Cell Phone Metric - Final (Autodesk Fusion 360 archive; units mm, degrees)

design "Cell Phone Metric - Final" references "Cell Phone Stand - Metric Assembly", "Vise"
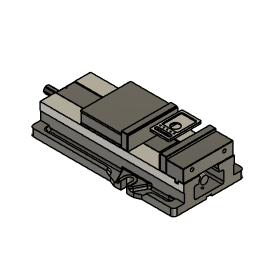
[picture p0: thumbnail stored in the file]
external_derived "ExternalDerived1"
align "Align1"
sketch "Sketch1" plane through (0, 0, 0) normal (0, 0, -1) x axis (1, 0, 0)
  line L1 (30, 46.5) -> (30, -46.5)
  line L2 (-26.5, 50) -> (26.5, 50)
  line L3 (-30, -46.5) -> (-30, 46.5)
  line L4 (26.5, -50) -> (-26.5, -50)
  line L5 (-23.5, 38.5) -> (-23.5, 36)
  line L6 (20, 42) -> (-20, 42)
  line L7 (23.5, 36) -> (23.5, 38.5)
  line L8 (-20, 32.5) -> (20, 32.5)
  line L9 (-50.8, -55) -> (50.8, -55)
  line L10 (-50.8, 55) -> (-50.8, -55)
  line L11 (50.8, 55) -> (-50.8, 55)
  line L12 (50.8, -55) -> (50.8, 55)
  line L13 (-50.8, 55) -> (50.8, -55)
  line L14 (50.8, 55) -> (-50.8, -55)
  arc A1 centre (26.5, -46.5) radius 3.5 clockwise from (30, -46.5) to (26.5, -50)
  arc A2 centre (26.5, 46.5) radius 3.5 clockwise from (26.5, 50) to (30, 46.5)
  arc A3 centre (-26.5, 46.5) radius 3.5 clockwise from (-30, 46.5) to (-26.5, 50)
  arc A4 centre (-26.5, -46.5) radius 3.5 clockwise from (-26.5, -50) to (-30, -46.5)
  circle C1 centre (10.5, 25) radius 2.117
  circle C2 centre (-10.5, 25) radius 2.117
  circle C3 centre (-21, 25) radius 2.117
  circle C4 centre (0, 25) radius 2.117
  circle C5 centre (21, 25) radius 2.117
  arc A5 centre (-20, 38.5) radius 3.5 clockwise from (-23.5, 38.5) to (-20, 42)
  arc A6 centre (20, 38.5) radius 3.5 clockwise from (20, 42) to (23.5, 38.5)
  arc A7 centre (20, 36) radius 3.5 clockwise from (23.5, 36) to (20, 32.5)
  arc A8 centre (-20, 36) radius 3.5 clockwise from (-20, 32.5) to (-23.5, 36)
  circle C6 centre (0, 0) radius 12.5
  point P36 (0, 0)
  point P1 (0, 0)
  point P34 (-50.8, 55)
  point P35 (50.8, 55)
  point P32 (50.8, -55)
  horizontal L9
  perpendicular L9 L10
  parallel L9 L11
  parallel L10 L12
  coincident L13 P36
  coincident L14 P36
  coincident P1 P36
  dimension "d1" distance P34 P35 = 101.6
  dimension "d2" distance P32 P35 = 110
extrude "Extrude1" new body sketch "Sketch1" profile of L9 L10 L11 L12 against normal blind 6 bodies "Stock"
component_insert "Component Insert"
position "Position1"
ground "Pin"
position "Position2"
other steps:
derived_base_feature "Derived Base Feature" bodies "Main Body"
named bodies: "Main Body", "Stock"

design "Vise"
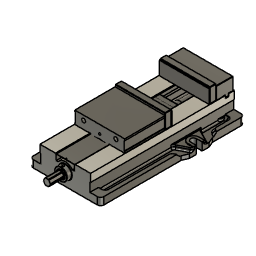
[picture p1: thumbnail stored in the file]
description: HaasClamp
base_feature "Base Feature1"
base_feature "Base Feature1"
base_feature "Base Feature1"
base_feature "Base Feature1"
base_feature "Base Feature1"
base_feature "Base Feature1"
base_feature "Base Feature1"
base_feature "Base Feature1"
base_feature "Base Feature1"
base_feature "Base Feature1"
as_built_joint "As-built1"
as_built_joint "As-built2"
as_built_joint "As-built3"
joint_origin "JointOrigin1" OffsetX 0 OffsetY 0 OffsetZ 0 AngleZ 0
joint "Assemble1" alignAngle 180 alignOffsetX 0 alignOffsetY 0 alignOffsetZ 0 (= "jaw_width_haas_050002") SlideMaximum 22.5 SlideMinimum 0
position "Position1"
sketch "Sketch1" plane through (0, -72.5, 0) normal (0, -1, 0) x axis (1, 0, 0)
  line L1 (75, 73) -> (-75, 73)
  line L2 (76, 74) -> (75, 73)
  line L3 (76, 116.5) -> (76, 74)
  line L4 (75, 117.5) -> (76, 116.5)
  line L5 (-75, 117.5) -> (75, 117.5)
  line L6 (-76, 116.5) -> (-75, 117.5)
  line L7 (-76, 74) -> (-76, 116.5)
  line L8 (-75, 73) -> (-76, 74)
  line L9 (76.4, 114.275) -> (-76, 114.275)
  line L10 (76.4, 73) -> (76.4, 114.275)
  line L11 (-76, 73) -> (76.4, 73)
  line L12 (-76, 114.275) -> (-76, 73)
  circle C1 centre (49.21, 96.8) radius 11
  circle C2 centre (-49.21, 96.8) radius 11
  point P14 (76.4, 73)
  point P12 (-76, 114.275)
  point P13 (76.4, 114.275)
  horizontal L9
  vertical L10
  horizontal L11
  vertical L12
  coincident L1 P14
  coincident L7 P12
  dimension "d16" distance P12 P13 = 152.4
  dimension "d17" distance P13 P14 = 41.275
place_component sketch "Sketch1"
extrude "Extrude1" new body sketch "Sketch1" profile of L1 L2 L3 L7 L8 C1 C2 L9 L11 L12 along normal blind 3.175
place_component sketch "Sketch1"
extrude "Extrude1" sketch "Sketch1" profile of L1 L2 L3 L7 L8 C1 C2 L9 L11 L12 blind -3.175
as_built_joint "As-built5"
as_built_joint "As-built6"
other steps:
create_component "CreateComponent1"
create_component "CreateComponent2"
create_component "CreateComponent3"
create_component "CreateComponent4"
create_component "CreateComponent5"
create_component "CreateComponent6"
create_component "CreateComponent7"
create_component "CreateComponent8"
create_component "CreateComponent9"
create_component "CreateComponent10"
joint_origin "JointOrigin10"
joint_origin "JointOrigin11"
create_component "CreateComponent11" sketch "Sketch1"
create_component "CreateComponent12" sketch "Sketch1"

design "Cell Phone Stand - Metric Assembly"
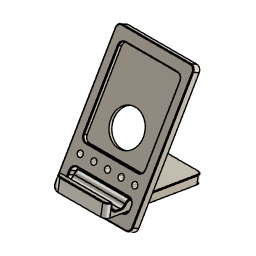
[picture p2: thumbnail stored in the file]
sketch "Main Body Sketch" plane through (0, 0, 0) normal (0, 1, 0) x axis (1, 0, 0)
  line L1 (30, 0) -> (-30, 0)
  line L2 (30, -100) -> (30, 0)
  line L3 (-30, -100) -> (30, -100)
  line L4 (-30, 0) -> (-30, -100)
  line L5 (30, -100) -> (-30, 0)
  line L6 (-30, -100) -> (30, 0)
  line L7 (23.5, -17.5) -> (-23.5, -17.5)
  line L8 (23.5, -8) -> (23.5, -17.5)
  line L9 (-23.5, -8) -> (23.5, -8)
  line L10 (-23.5, -17.5) -> (-23.5, -8)
  line L11 (0, 0) -> (0, -8)
  line L12 (23.5, -92) -> (-23.5, -92)
  line L13 (23.5, -32) -> (23.5, -92)
  line L14 (-23.5, -32) -> (23.5, -32)
  line L15 (-23.5, -92) -> (-23.5, -32)
  line L16 (0, -62.5) -> (0, -50)
  line L17 (17.2022, -62.0451) -> (0, -50)
  line L18 (21, -50) -> (0, -50)
  line L19 (17.2022, -37.9549) -> (0, -50)
  circle C1 centre (0, -50) radius 12.5
  point P6 (0, -50)
  point P1 (0, 0)
  point P11 (0, -8)
  point P12 (0, 0)
  point P17 (0, -50)
  point P21 (0, -50)
  point P22 (0, -62.5)
  point P18 (17.2022, -62.0451)
  point P23 (17.2022, -62.0451)
  point P19 (21, -50)
  point P24 (21, -50)
  point P25 (0, -50)
  point P20 (17.2022, -37.9549)
  point P26 (17.2022, -37.9549)
  point P27 (-17.2022, -62.0451)
  point P28 (-21, -50)
  point P29 (-17.2022, -37.9549)
  point P30 (0, -25)
  point P4 (30, -100)
  point P5 (-30, -100)
  point P3 (30, 0)
  point P8 (23.5, -17.5)
  point P9 (23.5, -8)
  point P7 (-23.5, -17.5)
  point P14 (23.5, -92)
  point P15 (23.5, -32)
  horizontal L1
  perpendicular L1 L2
  parallel L1 L3
  parallel L2 L4
  coincident L5 P6
  coincident L6 P6
  midpoint P1 L1
  horizontal L7
  vertical L8
  horizontal L9
  vertical L10
  midpoint L9 P11
  coincident P1 P12
  vertical L11
  horizontal L12
  vertical L13
  horizontal L14
  vertical L15
  collinear L8 L13
  collinear L10 L15
  coincident P6 P17
  coincident P6 P21
  coincident C1 P22
  vertical L16
  coincident P18 P23
  coincident P19 P24
  perpendicular L16 L18
  coincident P17 P25
  coincident P20 P26
  equal L17 L18
  equal L18 L19
  symmetric P18 L16 P27
  symmetric P19 L16 P28
  symmetric P20 L16 P29
  vertical P6 P30
  dimension "d1" distance P4 P5 = 60
  dimension "d2" distance P3 P4 = 100
  dimension "d3" distance P8 P9 = 9.5
  dimension "d4" distance L1 L9 = 8
  dimension "d5" distance P7 P8 = 47
  dimension "d6" distance L3 L12 = 8 (= "d4")
  dimension "d7" distance P14 P15 = 60
  dimension "d8" diameter C1 = 25
  dimension "d9" distance P21 P24 = 21
  dimension "d10" angle L17 L18 = 35
  dimension "d11" angle L18 L19 = 35 (= "d10")
  dimension "d12" distance P17 P30 = 25
  dimension "d15" R-Pattern1-uDistance = 21
  dimension "d16" R-Pattern1-vDistance = 0
extrude "Extrude1" new body sketch "Main Body Sketch" profile of L1 L2 L3 L4 L7 L8 L9 L10 L12 L13 L14 L15 C1 along normal blind 5.5
extrude "Extrude2" cut sketch "Main Body Sketch" profile of L12 L13 L14 L15 C1 along normal blind 3
hole "Hole2" HoleDiameter 4.234 TipAngle 118
fillet "Fillet1" radius 3.5
chamfer "Chamfer1" distance 0.5
move "Move1"
sketch "Stand Body Sketch" plane through (0, 0, 0) normal (1, 0, 0) x axis (0, 1, 0)
  line L1 (14.7999, 15.9408) -> (10.4698, 18.4408)
  line L2 (5.7198, 10.2135) -> (10.0499, 7.7135)
  line L3 (66.5456, 2.9579) -> (12.5794, 12.0948)
  line L4 (66.0448, 0) -> (66.5456, 2.9579)
  line L5 (-7.9029, 12.52) -> (66.0448, 0)
  line L6 (-6.317, 21.8867) -> (-7.9029, 12.52)
  line L7 (-2.3731, 21.2189) -> (-6.317, 21.8867)
  line L8 (-2.3281, 14.6188) -> (-2.3731, 21.2189)
  line L9 (6.5456, 13.1164) -> (-2.3281, 14.6188)
  line L10 (8.7802, 17.0486) -> (6.5456, 13.1164)
  line L11 (16.0467, 18.1003) -> (19.9906, 17.4326)
  line L12 (24.2831, 10.1133) -> (19.9906, 17.4326)
  line L13 (16.0467, 18.1003) -> (12.5794, 12.0948)
  line L14 (54.2999, 84.3568) -> (7.7999, 3.8164)
  line L15 (13.6992, 16.2157) -> (8.7802, 17.0486)
  line L16 (12.1028, 18.768) -> (11.7272, 16.5496)
  line L17 (16.0467, 18.1003) -> (12.1028, 18.768)
  line L18 (15.6711, 15.8819) -> (16.0467, 18.1003)
  line L19 (67.0881, 6.1623) -> (22.1368, 13.7729)
  line L20 (66.5456, 2.9579) -> (67.0881, 6.1623)
  circle C1 centre (13.6992, 16.2157) radius 2
  point P17 (24.2831, 10.1133)
  point P16 (16.0467, 18.1003)
  point P1 (0, 0)
  point P8 (66.0448, 0)
  point P18 (16.0467, 18.1003)
  point P5 (5.7198, 10.2135)
  point P23 (11.7272, 16.5496)
  point P26 (15.6711, 15.8819)
  point P21 (13.6992, 16.2157)
  point P22 (13.6992, 16.2157)
  point P25 (16.0467, 18.1003)
  point P28 (22.1368, 13.7729)
  point P30 (66.5456, 2.9579)
  point P7 (66.5456, 2.9579)
  point P9 (-7.9029, 12.52)
  point P10 (-6.317, 21.8867)
  point P11 (-2.3731, 21.2189)
  point P12 (-2.3281, 14.6188)
  point P13 (6.5456, 13.1164)
  point P15 (19.9906, 17.4326)
  point P14 (8.7802, 17.0486)
  point P27 (6.0499, 0.7853)
  perpendicular L3 L4
  perpendicular L5 L6
  perpendicular L6 L7
  parallel L3 L9
  coincident L3 P17
  collinear L7 L11
  perpendicular L1 L13
  coincident P16 L13
  parallel L3 L5
  horizontal P1 P8
  collinear L3 L9
  coincident P16 P18
  collinear L13 L14
  coincident P5 L5
  parallel L5 L15
  coincident C1 P23
  perpendicular L16 L17
  coincident C1 P26
  tangent C1 L18
  perpendicular L17 L18
  tangent C1 L16
  parallel L6 L16
  coincident P21 P22
  collinear L11 L17
  coincident P18 P25
  midpoint L12 P28
  perpendicular L4 L19
  coincident L3 P30
  perpendicular L3 L20
  coincident P7 P30
  dimension "d30" distance P8 P9 = 75
  dimension "d31" distance P7 P8 = 3
  dimension "d32" distance P9 P10 = 9.5
  dimension "d33" angle L11 L12 = 50
  dimension "d34" distance P10 P11 = 4
  dimension "d35" distance P12 P13 = 9
  dimension "d36" distance P15 P16 = 4
  dimension "d37" distance L9 P14 = 4.25
  dimension "d38" angle L9 L10 = 70
  dimension "d39" angle L8 L9 = 100
  dimension "d40" diameter C1 = 4
  dimension "d41" distance P8 P27 = 60
extrude "Extrude3" new body sketch "Stand Body Sketch" profile of L3 L4 L5 L6 L7 L8 L9 L10 L11 L12 L13 L14 L15 C1 L18 L19 L20 distance 40
fillet "Fillet2" radius 3.5
chamfer "Chamfer2" distance 0.5
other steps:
thread "Thread1" ThreadOffset 0 ThreadDepth 7.4
named bodies: "Main Body", "Stand Body"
